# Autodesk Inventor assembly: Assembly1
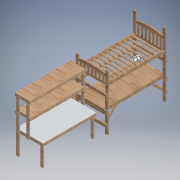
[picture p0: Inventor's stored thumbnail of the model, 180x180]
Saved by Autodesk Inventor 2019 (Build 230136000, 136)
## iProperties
Created: 2013-07
Part Number: Assembly1
Document SubType Name: Assembly
Designer: Patrick Rice
Author: Patrick Rice
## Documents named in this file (24)
- G:\hide08\projects\archive\room project\lofted bed with desk\Assembly1.iam
- G:\hide08\projects\archive\room project\lofted bed with desk\bed loft.ipt
- G:\hide08\projects\archive\room project\lofted bed with desk\table.ipt
- G:\hide08\projects\archive\room project\lofted bed with desk\ladder beam.ipt
- G:\hide08\projects\archive\room project\lofted bed with desk\ladder beam 2x6.ipt
- G:\hide08\projects\archive\room project\lofted bed with desk\main post 2x4.ipt
- G:\hide08\projects\archive\room project\lofted bed with desk\desk cross beam.ipt
- G:\hide08\projects\archive\room project\lofted bed with desk\desk support beam.ipt
- G:\hide08\projects\archive\room project\workbench desk\table top.ipt
- G:\hide08\projects\archive\room project\workbench desk\front desk underside support.ipt
- G:\hide08\projects\archive\room project\workbench desk\side desk underside support.ipt
- G:\hide08\projects\archive\room project\workbench desk\leg.ipt
- G:\hide08\projects\archive\room project\lofted bed with desk\ANSI B18.5 - 1_4-20 UNC - 3(8).ipt
- G:\hide08\projects\archive\room project\workbench desk\table crossbeam.ipt
- G:\hide08\projects\archive\room project\workbench desk\leg and shelf support.ipt
- G:\hide08\projects\archive\room project\workbench desk\shelf support.ipt
- G:\hide08\projects\archive\room project\workbench desk\shelf cross beam.ipt
- G:\hide08\projects\archive\room project\workbench desk\shelf plywood top top.ipt
- G:\hide08\projects\archive\room project\workbench desk\shelf plywood support.ipt
- G:\hide08\projects\archive\room project\workbench desk\shelf plywood top.ipt
- G:\hide08\projects\archive\room project\workbench desk\shelf plywood support edge.ipt
- G:\hide08\projects\archive\room project\workbench desk\plywood support outside.ipt
- G:\hide08\projects\archive\room project\lofted bed with desk\crossbeam.ipt
- G:\hide08\projects\archive\room project\lofted bed with desk\crossbeam long.ipt
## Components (87 placed, 24 different names)
1. crossbeam back:1 — Mate:442, Mate:448, Mate:449
2. crossbeam back:2 — Mate:444, Mate:446, Mate:447
3. crossbeam:3 — Mate:450, Mate:451, Mate:452
4. crossbeam:4 — Mate:454, Mate:455, Mate:456
5. crossbeam long:1 — Mate:457, Flush:203, Mate:458
6. Round Head Short Square Neck Bolt - Inch 1/4-20 UNC - 3:33 — Mate:298, Flush:161
7. Round Head Short Square Neck Bolt - Inch 1/4-20 UNC - 3:34 — Mate:301, Flush:164
8. Round Head Short Square Neck Bolt - Inch 1/4-20 UNC - 3:35 — Mate:299, Flush:162
9. Round Head Short Square Neck Bolt - Inch 1/4-20 UNC - 3:36 — Mate:300, Flush:163
10. ladder beam:6 — Flush:57, Flush:58, Mate:80, Mate:83, Mate:86, Mate:444, Mate:446, Mate:450, Mate:451, Mate:460
11. ladder beam:7 — Flush:55, Mate:74, Mate:77, Flush:64, Mate:82
12. main post 2x4:1 — Mate:50, Flush:35, Flush:36, Flush:39, Flush:40, Mate:51, Mate:52, Flush:41, Flush:60, Flush:68, Flush:69, Flush:164, Mate:307, Mate:448, Mate:458, Flush:204
13. main post 2x4:2 — Mate:48, Flush:31, Flush:32, Flush:42, Flush:61, Flush:66, Flush:70, Flush:73, Mate:97, Flush:74, Mate:105, Flush:163, Mate:456
14. main post 2x4:3 — Mate:77, Mate:78, Flush:62, Flush:63, Mate:80, Flush:64, Mate:81, Flush:65, Flush:71, Flush:161, Mate:452
15. main post 2x4:4 — Flush:53, Mate:72, Flush:54, Flush:55, Flush:56, Flush:57, Flush:58, Flush:59, Flush:67, Mate:91, Mate:98, Flush:162, Mate:447
16. ladder beam 2x6:1 — Mate:64, Flush:56, Mate:73, Mate:90, Mate:92, Mate:93, Mate:94, Mate:98, Flush:159, Mate:298, Mate:299, Mate:459
17. ladder beam 2x6:2 — Mate:88, Mate:89, Flush:73, Mate:96, Mate:97, Flush:74, Mate:104, Mate:107, Mate:108, Mate:300, Mate:301
18. desk cross beam:1 — Mate:309, Mate:310, Mate:311, Flush:165
19. desk cross beam:2 — Mate:316, Mate:317, Flush:165
20. desk cross beam:3 — Mate:312, Mate:314, Mate:315, Flush:205
21. desk support beam:1 — Mate:64, Mate:81, Mate:313, Mate:314, Mate:315, Flush:166, Flush:167
22. desk support beam:2 — Mate:104, Mate:105, Mate:308, Mate:310, Mate:311, Mate:317, Flush:168, Flush:169
23. Round Head Short Square Neck Bolt - Inch 1/4-20 UNC - 3:1 — Mate:75, Flush:60
24. Round Head Short Square Neck Bolt - Inch 1/4-20 UNC - 3:2 — Mate:76, Flush:61
25. Round Head Short Square Neck Bolt - Inch 1/4-20 UNC - 3:3 — Mate:82, Flush:65
26. Round Head Short Square Neck Bolt - Inch 1/4-20 UNC - 3:4 — Mate:83, Mate:460
27. Round Head Short Square Neck Bolt - Inch 1/4-20 UNC - 3:6 — Mate:85, Flush:66
28. Round Head Short Square Neck Bolt - Inch 1/4-20 UNC - 3:5 — Mate:74, Flush:59
29. Round Head Short Square Neck Bolt - Inch 1/4-20 UNC - 3:7 — Mate:86, Flush:67
30. Round Head Short Square Neck Bolt - Inch 1/4-20 UNC - 3:8 — Mate:87, Flush:68
31. Round Head Short Square Neck Bolt - Inch 1/4-20 UNC - 3:9 — Mate:88, Flush:69
32. Round Head Short Square Neck Bolt - Inch 1/4-20 UNC - 3:10 — Mate:89, Flush:70
33. Round Head Short Square Neck Bolt - Inch 1/4-20 UNC - 3:11 — Mate:90, Mate:91
34. Round Head Short Square Neck Bolt - Inch 1/4-20 UNC - 3:12 — Mate:92, Flush:71
35. Round Head Short Square Neck Bolt - Inch 1/4-20 UNC - 3:13 — Mate:107, Flush:168
36. Round Head Short Square Neck Bolt - Inch 1/4-20 UNC - 3:14 — Mate:108, Flush:169
37. Round Head Short Square Neck Bolt - Inch 1/4-20 UNC - 3:15 — Mate:94, Flush:166
38. Round Head Short Square Neck Bolt - Inch 1/4-20 UNC - 3:16 — Mate:93, Flush:167
39. bed loft:1 — Mate:48, Flush:31, Flush:32, Mate:50, Flush:35, Flush:36, Flush:53, Mate:72, Flush:54, Mate:78, Flush:62, Flush:63
40. ladder beam:1 — Flush:39, Flush:40, Mate:51, Mate:75, Mate:76, Mate:457, Flush:203
41. ladder beam:5 — Mate:52, Flush:41, Flush:42, Mate:85, Mate:87, Mate:442, Mate:449, Mate:454, Mate:455
42. table:1 — Mate:73, Mate:96, Flush:159, Mate:307, Mate:308, Mate:309, Mate:312, Mate:313, Mate:316
43. Round Head Short Square Neck Bolt - Inch 1/4-20 UNC - 3:37 — Mate:422, Flush:191
44. Round Head Short Square Neck Bolt - Inch 1/4-20 UNC - 3:38 — Mate:424, Flush:193
45. Round Head Short Square Neck Bolt - Inch 1/4-20 UNC - 3:39 — Mate:429, Flush:198
46. Round Head Short Square Neck Bolt - Inch 1/4-20 UNC - 3:40 — Mate:430, Mate:431
47. Round Head Short Square Neck Bolt - Inch 1/4-20 UNC - 3:41 — Mate:428, Flush:197
48. Round Head Short Square Neck Bolt - Inch 1/4-20 UNC - 3:42 — Mate:427, Flush:196
49. Round Head Short Square Neck Bolt - Inch 1/4-20 UNC - 3:43 — Mate:426, Flush:195
50. Round Head Short Square Neck Bolt - Inch 1/4-20 UNC - 3:44 — Mate:425, Flush:194
51. Round Head Short Square Neck Bolt - Inch 1/4-20 UNC - 3:45 — Mate:423, Flush:192
52. Round Head Short Square Neck Bolt - Inch 1/4-20 UNC - 3:46 — Mate:432, Flush:199
53. Round Head Short Square Neck Bolt - Inch 1/4-20 UNC - 3:47 — Mate:433, Flush:200
54. Round Head Short Square Neck Bolt - Inch 1/4-20 UNC - 3:48 — Mate:434, Mate:435
55. Round Head Short Square Neck Bolt - Inch 1/4-20 UNC - 3:49 — Mate:436, Flush:201
56. Round Head Short Square Neck Bolt - Inch 1/4-20 UNC - 3:50 — Mate:437, Flush:202
57. shelf plywood support edge:1 — Mate:391, Mate:392, Mate:393, Mate:394, Mate:419, Flush:196, Flush:197, Mate:439
58. shelf plywood support edge:2 — Mate:395, Mate:396, Mate:397, Mate:408, Flush:194, Flush:195
59. shelf plywood support edge:3 — Mate:399, Mate:400, Mate:401, Mate:407, Flush:200, Mate:435
60. shelf plywood support edge:4 — Mate:402, Mate:403, Mate:404, Mate:405, Mate:416, Flush:201, Flush:202
61. plywood support outside:4 — Mate:416, Mate:417, Mate:418
62. plywood support outside:5 — Mate:419, Mate:420, Mate:421
63. shelf plywood top:1 — Mate:337, Mate:338, Flush:183, Mate:339, Mate:351, Mate:354, Mate:360, Mate:397, Mate:401
64. shelf plywood support:5 — Mate:351, Mate:352, Mate:407
65. shelf plywood support:6 — Mate:349, Mate:380, Mate:405, Mate:406
66. shelf plywood support:7 — Mate:346, Mate:347, Mate:439
67. shelf plywood support:8 — Mate:354, Mate:355, Mate:362, Mate:408
68. shelf plywood support:9 — Mate:357, Mate:358, Mate:406
69. shelf plywood support:10 — Mate:360, Mate:361, Mate:362
70. shelf cross beam:1 — Mate:336, Flush:182, Mate:339, Mate:352, Mate:355, Mate:361, Mate:400
71. shelf cross beam:2 — Mate:337, Flush:183, Mate:384, Mate:386, Flush:188, Mate:396, Mate:398
72. shelf cross beam:3 — Flush:173, Mate:325, Flush:174, Mate:328, Flush:179
73. shelf cross beam:4 — Mate:327, Flush:180, Mate:347, Mate:358, Mate:377, Mate:380, Flush:190, Mate:392, Mate:404
74. shelf plywood top top:1 — Mate:328, Flush:179, Flush:180, Mate:346, Mate:349, Mate:357, Mate:377, Mate:378, Mate:388, Flush:189, Mate:393, Mate:402, Mate:417, Mate:421
75. leg and shelf support:1 — Flush:170, Mate:319, Mate:376, Flush:189, Mate:391, Mate:424, Mate:426, Mate:427
76. leg and shelf support:2 — Flush:171, Mate:321, Flush:173, Mate:325, Flush:174, Mate:336, Flush:182, Mate:338, Mate:363, Mate:373, Mate:403, Mate:418, Mate:430, Mate:434, Mate:437
77. shelf support:1 — Mate:327, Mate:378, Flush:190, Mate:394, Mate:395, Mate:398, Mate:420, Mate:423, Mate:425, Mate:428
78. shelf support:2 — Flush:187, Mate:385, Mate:386, Flush:188, Mate:388, Mate:399, Mate:432, Mate:433, Mate:436
79. table crossbeam:1 — Mate:226, Mate:228, Mate:370
80. table crossbeam:2 — Mate:229, Mate:231, Mate:369, Mate:372
81. table top:1 — Mate:139, Flush:97, Mate:226, Mate:229, Mate:365, Flush:185, Flush:186, Mate:368, Mate:375, Mate:384
82. front desk underside support:1 — Mate:118, Mate:122, Mate:130, Mate:131, Flush:91, Mate:139, Flush:97, Mate:228, Mate:364, Flush:184, Flush:186, Flush:205
83. front desk underside support:2 — Mate:231, Mate:319, Mate:321, Mate:367, Mate:368, Mate:373, Mate:374
84. side desk underside support:1 — Mate:372, Mate:374, Mate:375, Mate:376, Mate:390, Mate:422, Flush:192, Flush:193
85. side desk underside support:2 — Mate:363, Mate:364, Mate:365, Flush:184, Flush:185, Mate:367, Mate:369, Mate:370, Mate:381, Flush:187, Mate:385, Mate:429, Mate:431, Flush:199, Mate:459
86. leg:3 — Mate:118, Mate:131, Flush:91, Flush:170, Mate:390, Flush:191
87. leg:4 — Mate:122, Mate:130, Flush:171, Mate:381, Flush:198, Flush:204
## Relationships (227: Mate 156, Flush 71)
- Mate:48: main post 2x4:2 ↔ bed loft:1
- Flush:31: main post 2x4:2 ↔ bed loft:1
- Flush:32: main post 2x4:2 ↔ bed loft:1
- Mate:50: main post 2x4:1 ↔ bed loft:1
- Flush:35: main post 2x4:1 ↔ bed loft:1
- Flush:36: main post 2x4:1 ↔ bed loft:1
- Flush:39: main post 2x4:1 ↔ ladder beam:1
- Flush:40: main post 2x4:1 ↔ ladder beam:1
- Mate:51: main post 2x4:1 ↔ ladder beam:1
- Mate:52: main post 2x4:1 ↔ ladder beam:5
- Flush:41: main post 2x4:1 ↔ ladder beam:5
- Flush:42: main post 2x4:2 ↔ ladder beam:5
- Mate:64: ladder beam 2x6:1 ↔ desk support beam:1
- Flush:53: main post 2x4:4 ↔ bed loft:1
- Mate:72: main post 2x4:4 ↔ bed loft:1
- Flush:54: main post 2x4:4 ↔ bed loft:1
- Flush:55: ladder beam:7 ↔ main post 2x4:4
- Flush:56: main post 2x4:4 ↔ ladder beam 2x6:1
- Flush:57: ladder beam:6 ↔ main post 2x4:4
- Flush:58: ladder beam:6 ↔ main post 2x4:4
- Mate:73: ladder beam 2x6:1 ↔ table:1
- Mate:74: ladder beam:7 ↔ Round Head Short Square Neck Bolt - Inch 1/4-20 UNC - 3:5
- Flush:59: main post 2x4:4 ↔ Round Head Short Square Neck Bolt - Inch 1/4-20 UNC - 3:5
- Mate:75: Round Head Short Square Neck Bolt - Inch 1/4-20 UNC - 3:1 ↔ ladder beam:1
- Flush:60: main post 2x4:1 ↔ Round Head Short Square Neck Bolt - Inch 1/4-20 UNC - 3:1
- Mate:76: Round Head Short Square Neck Bolt - Inch 1/4-20 UNC - 3:2 ↔ ladder beam:1
- Flush:61: main post 2x4:2 ↔ Round Head Short Square Neck Bolt - Inch 1/4-20 UNC - 3:2
- Mate:77: ladder beam:7 ↔ main post 2x4:3
- Mate:78: main post 2x4:3 ↔ bed loft:1
- Flush:62: main post 2x4:3 ↔ bed loft:1
- Flush:63: main post 2x4:3 ↔ bed loft:1
- Mate:80: ladder beam:6 ↔ main post 2x4:3
- Flush:64: ladder beam:7 ↔ main post 2x4:3
- Mate:81: main post 2x4:3 ↔ desk support beam:1
- Mate:82: ladder beam:7 ↔ Round Head Short Square Neck Bolt - Inch 1/4-20 UNC - 3:3
- Flush:65: main post 2x4:3 ↔ Round Head Short Square Neck Bolt - Inch 1/4-20 UNC - 3:3
- Mate:83: ladder beam:6 ↔ Round Head Short Square Neck Bolt - Inch 1/4-20 UNC - 3:4
- Mate:85: Round Head Short Square Neck Bolt - Inch 1/4-20 UNC - 3:6 ↔ ladder beam:5
- Flush:66: main post 2x4:2 ↔ Round Head Short Square Neck Bolt - Inch 1/4-20 UNC - 3:6
- Mate:86: ladder beam:6 ↔ Round Head Short Square Neck Bolt - Inch 1/4-20 UNC - 3:7
- Flush:67: main post 2x4:4 ↔ Round Head Short Square Neck Bolt - Inch 1/4-20 UNC - 3:7
- Mate:87: Round Head Short Square Neck Bolt - Inch 1/4-20 UNC - 3:8 ↔ ladder beam:5
- Flush:68: main post 2x4:1 ↔ Round Head Short Square Neck Bolt - Inch 1/4-20 UNC - 3:8
- Mate:88: ladder beam 2x6:2 ↔ Round Head Short Square Neck Bolt - Inch 1/4-20 UNC - 3:9
- Flush:69: main post 2x4:1 ↔ Round Head Short Square Neck Bolt - Inch 1/4-20 UNC - 3:9
- Mate:89: ladder beam 2x6:2 ↔ Round Head Short Square Neck Bolt - Inch 1/4-20 UNC - 3:10
- Flush:70: main post 2x4:2 ↔ Round Head Short Square Neck Bolt - Inch 1/4-20 UNC - 3:10
- Mate:90: ladder beam 2x6:1 ↔ Round Head Short Square Neck Bolt - Inch 1/4-20 UNC - 3:11
- Mate:91: main post 2x4:4 ↔ Round Head Short Square Neck Bolt - Inch 1/4-20 UNC - 3:11
- Mate:92: ladder beam 2x6:1 ↔ Round Head Short Square Neck Bolt - Inch 1/4-20 UNC - 3:12
- Flush:71: main post 2x4:3 ↔ Round Head Short Square Neck Bolt - Inch 1/4-20 UNC - 3:12
- Mate:93: ladder beam 2x6:1 ↔ Round Head Short Square Neck Bolt - Inch 1/4-20 UNC - 3:16
- Mate:94: ladder beam 2x6:1 ↔ Round Head Short Square Neck Bolt - Inch 1/4-20 UNC - 3:15
- Flush:73: main post 2x4:2 ↔ ladder beam 2x6:2
- Mate:96: ladder beam 2x6:2 ↔ table:1
- Mate:97: main post 2x4:2 ↔ ladder beam 2x6:2
- Flush:74: main post 2x4:2 ↔ ladder beam 2x6:2
- Mate:98: main post 2x4:4 ↔ ladder beam 2x6:1
- Mate:104: ladder beam 2x6:2 ↔ desk support beam:2
- Mate:105: main post 2x4:2 ↔ desk support beam:2
- Mate:107: ladder beam 2x6:2 ↔ Round Head Short Square Neck Bolt - Inch 1/4-20 UNC - 3:13
- Mate:108: ladder beam 2x6:2 ↔ Round Head Short Square Neck Bolt - Inch 1/4-20 UNC - 3:14
- Mate:118: front desk underside support:1 ↔ leg:3
- Mate:122: front desk underside support:1 ↔ leg:4
- Mate:130: front desk underside support:1 ↔ leg:4
- Mate:131: front desk underside support:1 ↔ leg:3
- Flush:91: front desk underside support:1 ↔ leg:3
- Mate:139: table top:1 ↔ front desk underside support:1
- Flush:97: table top:1 ↔ front desk underside support:1
- Mate:226: table crossbeam:1 ↔ table top:1
- Mate:228: table crossbeam:1 ↔ front desk underside support:1
- Mate:229: table crossbeam:2 ↔ table top:1
- Mate:231: table crossbeam:2 ↔ front desk underside support:2
- Flush:159: ladder beam 2x6:1 ↔ table:1
- Mate:298: Round Head Short Square Neck Bolt - Inch 1/4-20 UNC - 3:33 ↔ ladder beam 2x6:1
- Flush:161: Round Head Short Square Neck Bolt - Inch 1/4-20 UNC - 3:33 ↔ main post 2x4:3
- Mate:299: Round Head Short Square Neck Bolt - Inch 1/4-20 UNC - 3:35 ↔ ladder beam 2x6:1
- Flush:162: Round Head Short Square Neck Bolt - Inch 1/4-20 UNC - 3:35 ↔ main post 2x4:4
- Mate:300: Round Head Short Square Neck Bolt - Inch 1/4-20 UNC - 3:36 ↔ ladder beam 2x6:2
- Flush:163: Round Head Short Square Neck Bolt - Inch 1/4-20 UNC - 3:36 ↔ main post 2x4:2
- Mate:301: Round Head Short Square Neck Bolt - Inch 1/4-20 UNC - 3:34 ↔ ladder beam 2x6:2
- Flush:164: Round Head Short Square Neck Bolt - Inch 1/4-20 UNC - 3:34 ↔ main post 2x4:1
- Mate:307: main post 2x4:1 ↔ table:1
- Mate:308: desk support beam:2 ↔ table:1
- Mate:309: desk cross beam:1 ↔ table:1
- Mate:310: desk cross beam:1 ↔ desk support beam:2
- Mate:311: desk cross beam:1 ↔ desk support beam:2
- Mate:312: desk cross beam:3 ↔ table:1
- Mate:313: desk support beam:1 ↔ table:1
- Mate:314: desk cross beam:3 ↔ desk support beam:1
- Mate:315: desk cross beam:3 ↔ desk support beam:1
- Mate:316: desk cross beam:2 ↔ table:1
- Mate:317: desk cross beam:2 ↔ desk support beam:2
- Flush:165: desk cross beam:1 ↔ desk cross beam:2
- Flush:166: desk support beam:1 ↔ Round Head Short Square Neck Bolt - Inch 1/4-20 UNC - 3:15
- Flush:167: desk support beam:1 ↔ Round Head Short Square Neck Bolt - Inch 1/4-20 UNC - 3:16
- Flush:168: desk support beam:2 ↔ Round Head Short Square Neck Bolt - Inch 1/4-20 UNC - 3:13
- Flush:169: desk support beam:2 ↔ Round Head Short Square Neck Bolt - Inch 1/4-20 UNC - 3:14
- Flush:170: leg and shelf support:1 ↔ leg:3
- Mate:319: leg and shelf support:1 ↔ front desk underside support:2
- Flush:171: leg and shelf support:2 ↔ leg:4
- Mate:321: leg and shelf support:2 ↔ front desk underside support:2
- Flush:173: shelf cross beam:3 ↔ leg and shelf support:2
- Mate:325: shelf cross beam:3 ↔ leg and shelf support:2
- Flush:174: shelf cross beam:3 ↔ leg and shelf support:2
- Mate:327: shelf cross beam:4 ↔ shelf support:1
- Mate:328: shelf cross beam:3 ↔ shelf plywood top top:1
- Flush:179: shelf cross beam:3 ↔ shelf plywood top top:1
- Flush:180: shelf cross beam:4 ↔ shelf plywood top top:1
- Mate:336: shelf cross beam:1 ↔ leg and shelf support:2
- Flush:182: shelf cross beam:1 ↔ leg and shelf support:2
- Mate:337: shelf plywood top:1 ↔ shelf cross beam:2
- Mate:338: shelf plywood top:1 ↔ leg and shelf support:2
- Flush:183: shelf plywood top:1 ↔ shelf cross beam:2
- Mate:339: shelf plywood top:1 ↔ shelf cross beam:1
- Mate:346: shelf plywood support:7 ↔ shelf plywood top top:1
- Mate:347: shelf plywood support:7 ↔ shelf cross beam:4
- Mate:349: shelf plywood support:6 ↔ shelf plywood top top:1
- Mate:351: shelf plywood top:1 ↔ shelf plywood support:5
- Mate:352: shelf plywood support:5 ↔ shelf cross beam:1
- Mate:354: shelf plywood top:1 ↔ shelf plywood support:8
- Mate:355: shelf plywood support:8 ↔ shelf cross beam:1
- Mate:357: shelf plywood support:9 ↔ shelf plywood top top:1
- Mate:358: shelf plywood support:9 ↔ shelf cross beam:4
- Mate:360: shelf plywood top:1 ↔ shelf plywood support:10
- Mate:361: shelf plywood support:10 ↔ shelf cross beam:1
- Mate:362: shelf plywood support:8 ↔ shelf plywood support:10
- Mate:363: leg and shelf support:2 ↔ side desk underside support:2
- Mate:364: front desk underside support:1 ↔ side desk underside support:2
- Mate:365: table top:1 ↔ side desk underside support:2
- Flush:184: front desk underside support:1 ↔ side desk underside support:2
- Flush:185: table top:1 ↔ side desk underside support:2
- Flush:186: table top:1 ↔ front desk underside support:1
- Mate:367: front desk underside support:2 ↔ side desk underside support:2
- Mate:368: table top:1 ↔ front desk underside support:2
- Mate:369: table crossbeam:2 ↔ side desk underside support:2
- Mate:370: table crossbeam:1 ↔ side desk underside support:2
- Mate:372: table crossbeam:2 ↔ side desk underside support:1
- Mate:373: leg and shelf support:2 ↔ front desk underside support:2
- Mate:374: front desk underside support:2 ↔ side desk underside support:1
- Mate:375: table top:1 ↔ side desk underside support:1
- Mate:376: leg and shelf support:1 ↔ side desk underside support:1
- Mate:377: shelf cross beam:4 ↔ shelf plywood top top:1
- Mate:378: shelf plywood top top:1 ↔ shelf support:1
- Mate:380: shelf plywood support:6 ↔ shelf cross beam:4
- Mate:381: side desk underside support:2 ↔ leg:4
- Mate:384: shelf cross beam:2 ↔ table top:1
- Flush:187: shelf support:2 ↔ side desk underside support:2
- Mate:385: shelf support:2 ↔ side desk underside support:2
- Mate:386: shelf cross beam:2 ↔ shelf support:2
- Flush:188: shelf cross beam:2 ↔ shelf support:2
- Mate:388: shelf plywood top top:1 ↔ shelf support:2
- Flush:189: shelf plywood top top:1 ↔ leg and shelf support:1
- Mate:390: side desk underside support:1 ↔ leg:3
- Flush:190: shelf cross beam:4 ↔ shelf support:1
- Mate:391: shelf plywood support edge:1 ↔ leg and shelf support:1
- Mate:392: shelf plywood support edge:1 ↔ shelf cross beam:4
- Mate:393: shelf plywood support edge:1 ↔ shelf plywood top top:1
- Mate:394: shelf plywood support edge:1 ↔ shelf support:1
- Mate:395: shelf plywood support edge:2 ↔ shelf support:1
- Mate:396: shelf plywood support edge:2 ↔ shelf cross beam:2
- Mate:397: shelf plywood support edge:2 ↔ shelf plywood top:1
- Mate:398: shelf cross beam:2 ↔ shelf support:1
- Mate:399: shelf plywood support edge:3 ↔ shelf support:2
- Mate:400: shelf plywood support edge:3 ↔ shelf cross beam:1
- Mate:401: shelf plywood support edge:3 ↔ shelf plywood top:1
- Mate:402: shelf plywood support edge:4 ↔ shelf plywood top top:1
- Mate:403: shelf plywood support edge:4 ↔ leg and shelf support:2
- Mate:404: shelf plywood support edge:4 ↔ shelf cross beam:4
- Mate:405: shelf plywood support edge:4 ↔ shelf plywood support:6
- Mate:406: shelf plywood support:6 ↔ shelf plywood support:9
- Mate:407: shelf plywood support edge:3 ↔ shelf plywood support:5
- Mate:408: shelf plywood support edge:2 ↔ shelf plywood support:8
- Mate:416: shelf plywood support edge:4 ↔ plywood support outside:4
- Mate:417: plywood support outside:4 ↔ shelf plywood top top:1
- Mate:418: plywood support outside:4 ↔ leg and shelf support:2
- Mate:419: shelf plywood support edge:1 ↔ plywood support outside:5
- Mate:420: plywood support outside:5 ↔ shelf support:1
- Mate:421: plywood support outside:5 ↔ shelf plywood top top:1
- Mate:422: Round Head Short Square Neck Bolt - Inch 1/4-20 UNC - 3:37 ↔ side desk underside support:1
- Flush:191: Round Head Short Square Neck Bolt - Inch 1/4-20 UNC - 3:37 ↔ leg:3
- Mate:423: Round Head Short Square Neck Bolt - Inch 1/4-20 UNC - 3:45 ↔ shelf support:1
- Flush:192: Round Head Short Square Neck Bolt - Inch 1/4-20 UNC - 3:45 ↔ side desk underside support:1
- Mate:424: Round Head Short Square Neck Bolt - Inch 1/4-20 UNC - 3:38 ↔ leg and shelf support:1
- Flush:193: Round Head Short Square Neck Bolt - Inch 1/4-20 UNC - 3:38 ↔ side desk underside support:1
- Mate:425: Round Head Short Square Neck Bolt - Inch 1/4-20 UNC - 3:44 ↔ shelf support:1
- Flush:194: Round Head Short Square Neck Bolt - Inch 1/4-20 UNC - 3:44 ↔ shelf plywood support edge:2
- Mate:426: Round Head Short Square Neck Bolt - Inch 1/4-20 UNC - 3:43 ↔ leg and shelf support:1
- Flush:195: Round Head Short Square Neck Bolt - Inch 1/4-20 UNC - 3:43 ↔ shelf plywood support edge:2
- Mate:427: Round Head Short Square Neck Bolt - Inch 1/4-20 UNC - 3:42 ↔ leg and shelf support:1
- Flush:196: Round Head Short Square Neck Bolt - Inch 1/4-20 UNC - 3:42 ↔ shelf plywood support edge:1
- Mate:428: Round Head Short Square Neck Bolt - Inch 1/4-20 UNC - 3:41 ↔ shelf support:1
- Flush:197: Round Head Short Square Neck Bolt - Inch 1/4-20 UNC - 3:41 ↔ shelf plywood support edge:1
- Mate:429: Round Head Short Square Neck Bolt - Inch 1/4-20 UNC - 3:39 ↔ side desk underside support:2
- Flush:198: Round Head Short Square Neck Bolt - Inch 1/4-20 UNC - 3:39 ↔ leg:4
- Mate:430: Round Head Short Square Neck Bolt - Inch 1/4-20 UNC - 3:40 ↔ leg and shelf support:2
- Mate:431: Round Head Short Square Neck Bolt - Inch 1/4-20 UNC - 3:40 ↔ side desk underside support:2
- Mate:432: Round Head Short Square Neck Bolt - Inch 1/4-20 UNC - 3:46 ↔ shelf support:2
- Flush:199: Round Head Short Square Neck Bolt - Inch 1/4-20 UNC - 3:46 ↔ side desk underside support:2
- Mate:433: Round Head Short Square Neck Bolt - Inch 1/4-20 UNC - 3:47 ↔ shelf support:2
- Flush:200: Round Head Short Square Neck Bolt - Inch 1/4-20 UNC - 3:47 ↔ shelf plywood support edge:3
- Mate:434: Round Head Short Square Neck Bolt - Inch 1/4-20 UNC - 3:48 ↔ leg and shelf support:2
- Mate:435: Round Head Short Square Neck Bolt - Inch 1/4-20 UNC - 3:48 ↔ shelf plywood support edge:3
- Mate:436: Round Head Short Square Neck Bolt - Inch 1/4-20 UNC - 3:49 ↔ shelf support:2
- Flush:201: Round Head Short Square Neck Bolt - Inch 1/4-20 UNC - 3:49 ↔ shelf plywood support edge:4
- Mate:437: Round Head Short Square Neck Bolt - Inch 1/4-20 UNC - 3:50 ↔ leg and shelf support:2
- Flush:202: Round Head Short Square Neck Bolt - Inch 1/4-20 UNC - 3:50 ↔ shelf plywood support edge:4
- Mate:439: shelf plywood support edge:1 ↔ shelf plywood support:7
- Mate:442: crossbeam back:1 ↔ ladder beam:5
- Mate:444: crossbeam back:2 ↔ ladder beam:6
- Mate:446: crossbeam back:2 ↔ ladder beam:6
- Mate:447: crossbeam back:2 ↔ main post 2x4:4
- Mate:448: crossbeam back:1 ↔ main post 2x4:1
- Mate:449: crossbeam back:1 ↔ ladder beam:5
- Mate:450: crossbeam:3 ↔ ladder beam:6
- Mate:451: crossbeam:3 ↔ ladder beam:6
- Mate:452: crossbeam:3 ↔ main post 2x4:3
- Mate:454: crossbeam:4 ↔ ladder beam:5
- Mate:455: crossbeam:4 ↔ ladder beam:5
- Mate:456: crossbeam:4 ↔ main post 2x4:2
- Mate:457: crossbeam long:1 ↔ ladder beam:1
- Flush:203: crossbeam long:1 ↔ ladder beam:1
- Mate:458: crossbeam long:1 ↔ main post 2x4:1
- Flush:204: main post 2x4:1 ↔ leg:4
- Mate:459: ladder beam 2x6:1 ↔ side desk underside support:2
- Flush:205: desk cross beam:3 ↔ front desk underside support:1
- Mate:460: ladder beam:6 ↔ Round Head Short Square Neck Bolt - Inch 1/4-20 UNC - 3:4
